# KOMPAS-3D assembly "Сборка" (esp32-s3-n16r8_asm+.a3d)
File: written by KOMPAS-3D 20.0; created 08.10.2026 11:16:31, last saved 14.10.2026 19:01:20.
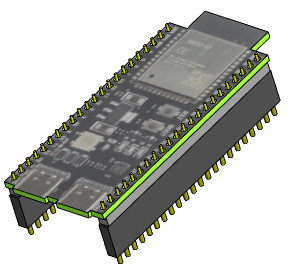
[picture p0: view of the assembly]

Document properties: Полное имя файла: D:\myProjects\Progect_esp32\box_compas\esp32\esp32-s3-n16r8_asm+.a3d

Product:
- Part/product: Сборка
    Масса: 0.0386432
  - Component [detail]: Деталь  | qty 2  | Масса: 0.00672836; source file: ..\разъемы\pbs_22.m3d
  - Component [detail]: Деталь  | qty 2  | Масса: 0.00286774; source file: ..\разъемы\pls_22.m3d
  - Component [detail]: Деталь  | Масса: 0.019451; source file: esp32-s3-n16r8.m3d

Referenced files in D:\myProjects\Progect_esp32\box_compas\esp32\: esp32-s3-n16r8.m3d
Referenced files in D:\myProjects\Progect_esp32\box_compas\разъемы\: pls_22.m3d, pbs_22.m3d
Referenced files in D:\RicWork\Project-EPS32\box_compas\разъемы\: pls_22.m3d
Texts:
  Деталь (1)
  Деталь (2)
